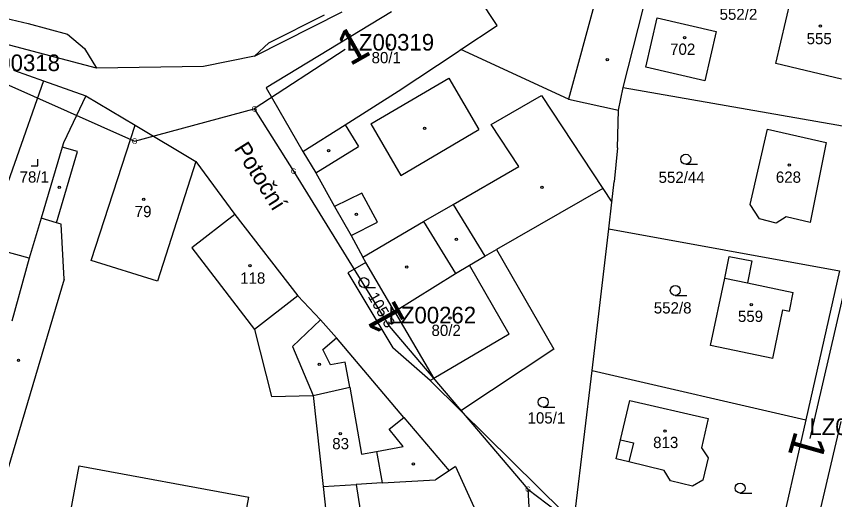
# Model space of a CAD drawing. Extents: x -738131 to -734179, y -1033447 to -1030078.
# Drawn here: x -735973.3 to -735849.9, y -1032032.1 to -1031959.2 of the extents above; entities that cross this region are included whole.
import ezdxf

# ---------------------------------------------------------------- set-up
doc = ezdxf.new("R2010")
doc.units = 0
for name, color, linetype in [('ftf_2010', 7, 'Continuous'), ('ftf_2050', 7, 'Continuous'), ('ftf_3010', 7, 'Continuous'), ('ftf_3010_ftf_3010_gtda_3015_gtda_3015_1', 7, 'Continuous'), ('ftf_3240', 7, 'Continuous'), ('ftf_nu', 7, 'Continuous'), ('Vrstva 1', 7, 'Continuous'), ('Vrstva 2', 7, 'Continuous'), ('Vrstva 3', 7, 'Continuous'), ('Vrstva 4', 7, 'Continuous'), ('Vrstva 5', 7, 'Continuous')]:
    doc.layers.add(name, color=color, linetype=linetype)

msp = doc.modelspace()

# ---------------------------------------------------------------- linework, layer by layer
at = {"layer": 'ftf_2010'}
for points in [[(-735923.72, -1031964.24), (-735937.43, -1031973.19)], [(-735853.59, -1032022.89), (-735843.74, -1031980.38)], [(-735896.17, -1032030.54), (-735890.35, -1032034.94), (-735881.54, -1032037.71)]]:
    msp.add_lwpolyline(points, dxfattribs=at)
at = {"layer": 'ftf_2050'}
for points in [[(-735980.93, -1031966.75), (-735955.51, -1031978.05), (-735937.43, -1031973.19), (-735931.52, -1031982.59), (-735917.1, -1032005.94)], [(-735917.1, -1032005.94), (-735896.17, -1032030.54)], [(-735896.17, -1032030.54), (-735893.12, -1032084.54)]]:
    msp.add_lwpolyline(points, dxfattribs=at)
at = {"layer": 'Vrstva 1'}
for points in [[(-735961.21, -1031967.08), (-736018.7, -1031951.81)], [(-735900.79, -1031960.62), (-735906.3, -1031952.23)], [(-735986.96, -1031956.67), (-735971.51, -1031960.34)], [(-735858.78, -1031966.37), (-735856.49, -1031956.68)], [(-735937.37, -1031965.26), (-735924.17, -1031958.55)], [(-735916.75, -1031958.57), (-735935.65, -1031970.03)], [(-735935.21, -1031963.22), (-735926.83, -1031959.03)], [(-735881.77, -1031969.95), (-735878.78, -1031958.13)], [(-735971.51, -1031960.34), (-735965.62, -1031961.95)], [(-735878.36, -1031966.91), (-735876.65, -1031959.47)], [(-735876.65, -1031959.47), (-735867.74, -1031961.53)], [(-735906.29, -1031964.27), (-735900.79, -1031960.62)], [(-735867.74, -1031961.53), (-735869.45, -1031968.95)], [(-735965.62, -1031961.95), (-735963.02, -1031964.11)], [(-735963.02, -1031964.11), (-735961.21, -1031967.08)], [(-735937.37, -1031965.26), (-735935.21, -1031963.22)], [(-735937.37, -1031965.26), (-735945.11, -1031966.83)], [(-735890.02, -1031971.71), (-735906.29, -1031964.27)], [(-735848.86, -1031968.72), (-735858.78, -1031966.37)], [(-735973.72, -1031967.37), (-735969.23, -1031968.95)], [(-735945.11, -1031966.83), (-735961.21, -1031967.08)], [(-735869.45, -1031968.95), (-735878.36, -1031966.91)], [(-735969.23, -1031968.95), (-735978.02, -1031993.89)], [(-735969.23, -1031968.95), (-735962.81, -1031971.21)], [(-735935.65, -1031970.03), (-735930.11, -1031979.64)], [(-735882.47, -1031973.38), (-735881.77, -1031969.95)], [(-735881.77, -1031969.95), (-735844.37, -1031976.51)], [(-735962.81, -1031971.21), (-735966.2, -1031978.32)], [(-735962.81, -1031971.21), (-735955.41, -1031975.66)], [(-735890.02, -1031971.71), (-735882.47, -1031973.38)], [(-735882.65, -1031979.08), (-735882.47, -1031973.38)], [(-735955.41, -1031975.66), (-735946.22, -1031981.15)], [(-735862.66, -1031987.59), (-735860.01, -1031976.28)], [(-735860.01, -1031976.28), (-735851.15, -1031978.27)], [(-735966.39, -1031978.96), (-735969.58, -1031989.67)], [(-735966.2, -1031978.32), (-735966.39, -1031978.96)], [(-735851.15, -1031978.27), (-735853.6, -1031990.31)], [(-735930.11, -1031979.64), (-735928.14, -1031982.86)], [(-735882.65, -1031979.08), (-735883.13, -1031984.22)], [(-735946.22, -1031981.15), (-735940.38, -1031989.1)], [(-735928.14, -1031982.86), (-735925.34, -1031987.91)], [(-735884.86, -1031985.2), (-735900.89, -1031994.4)], [(-735884.86, -1031985.2), (-735883.49, -1031987.28)], [(-735883.49, -1031987.28), (-735883.13, -1031984.22)], [(-735911.88, -1031990.2), (-735907.41, -1031987.6)], [(-735907.41, -1031987.6), (-735902.63, -1031995.4)], [(-735883.96, -1031991.27), (-735883.49, -1031987.28)], [(-735861.25, -1031989.8), (-735862.66, -1031987.59)], [(-735925.34, -1031987.91), (-735922.83, -1031992.3)], [(-735969.58, -1031989.67), (-735971.38, -1031995.71)], [(-735940.38, -1031989.1), (-735946.87, -1031994.13)], [(-735940.38, -1031989.1), (-735930.85, -1032001.38)], [(-735858.7, -1031990.42), (-735861.25, -1031989.8)], [(-735857.21, -1031989.47), (-735858.7, -1031990.42)], [(-735853.6, -1031990.31), (-735857.21, -1031989.47)], [(-735921.06, -1031995.58), (-735911.88, -1031990.2)], [(-735886.49, -1032012.63), (-735883.96, -1031991.27)], [(-735883.96, -1031991.27), (-735849.15, -1031997.63)], [(-735922.83, -1031992.3), (-735921.06, -1031995.58)], [(-735971.38, -1031995.71), (-735978.02, -1031993.89)], [(-735946.87, -1031994.13), (-735937.4, -1032006.46)], [(-735902.63, -1031995.4), (-735900.89, -1031994.4)], [(-735900.89, -1031994.4), (-735892.26, -1032009.45)], [(-735971.38, -1031995.71), (-735973.98, -1032005.19)], [(-735920.62, -1031996.34), (-735923.3, -1031997.93)], [(-735920.62, -1031996.34), (-735921.06, -1031995.58)], [(-735916.28, -1032003.73), (-735920.62, -1031996.34)], [(-735866.48, -1031998.72), (-735865.79, -1031995.43)], [(-735865.79, -1031995.43), (-735862.36, -1031996.13)], [(-735862.36, -1031996.13), (-735863.06, -1031999.44)], [(-735923.3, -1031997.93), (-735916.55, -1032009.23)], [(-735868.61, -1032008.87), (-735866.48, -1031998.72)], [(-735849.15, -1031997.63), (-735854.24, -1032020.1)], [(-735863.06, -1031999.44), (-735856.14, -1032000.89)], [(-735856.72, -1032003.69), (-735856.14, -1032000.89)], [(-735930.85, -1032001.38), (-735927.46, -1032005)], [(-735916.28, -1032003.73), (-735910.35, -1032013.83)], [(-735859.24, -1032010.84), (-735857.7, -1032003.48)], [(-735857.7, -1032003.48), (-735856.72, -1032003.69)], [(-735927.46, -1032005), (-735931.64, -1032009.01)], [(-735925.04, -1032007.7), (-735927.46, -1032005)], [(-735937.4, -1032006.46), (-735934.81, -1032016.56)], [(-735914.87, -1032019.71), (-735925.04, -1032007.7)], [(-735931.64, -1032009.01), (-735928.55, -1032016.39)], [(-735910.91, -1032014.16), (-735916.55, -1032009.23)], [(-735892.26, -1032009.45), (-735906.26, -1032018.74)], [(-735859.24, -1032010.84), (-735868.61, -1032008.87)], [(-735888.96, -1032033.55), (-735886.49, -1032012.63)], [(-735886.49, -1032012.63), (-735854.24, -1032020.1)], [(-735910.35, -1032013.83), (-735910.91, -1032014.16)], [(-735910.91, -1032014.16), (-735906.26, -1032018.74)], [(-735934.81, -1032016.56), (-735928.55, -1032016.39)], [(-735928.55, -1032016.39), (-735927.06, -1032030.11)], [(-735882.17, -1032023.1), (-735880.8, -1032017.15)], [(-735880.8, -1032017.15), (-735868.98, -1032019.87)], [(-735914.87, -1032019.71), (-735908.01, -1032027.75)], [(-735890.86, -1032033.93), (-735906.26, -1032018.74)], [(-735868.98, -1032019.87), (-735869.98, -1032024.28)], [(-735854.24, -1032020.1), (-735858.7, -1032039.76)], [(-735848.94, -1032020.31), (-735854.11, -1032042.18)], [(-735882.83, -1032025.98), (-735882.17, -1032023.1)], [(-735869.98, -1032024.28), (-735868.99, -1032025.83)], [(-735868.99, -1032025.83), (-735869.78, -1032029.16)], [(-735907.07, -1032027.13), (-735908.01, -1032027.75)], [(-735907.07, -1032027.13), (-735904.32, -1032033.19)], [(-735880.94, -1032026.43), (-735882.83, -1032025.98)], [(-735875.6, -1032027.72), (-735880.94, -1032026.43)], [(-735908.01, -1032027.75), (-735910.12, -1032029.14)], [(-735874.67, -1032029.29), (-735875.6, -1032027.72)], [(-735918.12, -1032029.6), (-735922.07, -1032029.83)], [(-735918.12, -1032029.6), (-735910.12, -1032029.14)], [(-735871.31, -1032030.08), (-735874.67, -1032029.29)], [(-735869.78, -1032029.16), (-735871.31, -1032030.08)], [(-735927.06, -1032030.11), (-735922.07, -1032029.83)], [(-735927.06, -1032030.11), (-735924.89, -1032050.16)], [(-735922.07, -1032029.83), (-735920.93, -1032036.93)]]:
    msp.add_lwpolyline(points, dxfattribs=at)
at = {"layer": 'Vrstva 3'}
for p, q in [((-735970.09, -1031981.78), (-735970.09, -1031980.78)), ((-735971.09, -1031981.78), (-735970.09, -1031981.78)), ((-735872.35, -1031981.54), (-735870.6, -1031981.54)), ((-735920.89, -1032000.14), (-735919.14, -1032000.14)), ((-735873.93, -1032001.32), (-735872.18, -1032001.32)), ((-735893.85, -1032018.17), (-735892.1, -1032018.17)), ((-735864.15, -1032031.12), (-735862.4, -1032031.12))]:
    msp.add_line(p, q, dxfattribs=at)
for centre in [(-735872.35, -1031980.79), (-735920.89, -1031999.39), (-735873.93, -1032000.57), (-735893.85, -1032017.42), (-735864.15, -1032030.37)]:
    msp.add_circle(centre, 0.75, dxfattribs=at)
at = {"layer": 'Vrstva 4'}
for points in [[(-735885.93, -1031956.55), (-735890.02, -1031971.71)], [(-735915.73, -1031970.51), (-735906.84, -1031964.63)], [(-735906.84, -1031964.63), (-735906.29, -1031964.27)], [(-735919.85, -1031975.47), (-735908.09, -1031968.57)], [(-735908.09, -1031968.57), (-735903.55, -1031976.32)], [(-735923.73, -1031975.59), (-735915.73, -1031970.51)], [(-735901.7, -1031975.55), (-735894.13, -1031971.16)], [(-735894.13, -1031971.16), (-735884.86, -1031985.2)], [(-735962.04, -1031996.06), (-735955.41, -1031975.66)], [(-735930.11, -1031979.64), (-735923.73, -1031975.59)], [(-735923.73, -1031975.59), (-735921.73, -1031978.85)], [(-735919.85, -1031975.47), (-735915.31, -1031983.22)], [(-735915.31, -1031983.22), (-735903.55, -1031976.32)], [(-735897.53, -1031981.87), (-735901.7, -1031975.55)], [(-735964.09, -1031979.63), (-735966.39, -1031978.96)], [(-735928.14, -1031982.86), (-735921.73, -1031978.85)], [(-735967.28, -1031990.37), (-735964.09, -1031979.63)], [(-735946.22, -1031981.15), (-735952.03, -1031999.15)], [(-735907.41, -1031987.6), (-735897.53, -1031981.87)], [(-735921.2, -1031985.89), (-735925.34, -1031987.91)], [(-735918.84, -1031990.27), (-735921.2, -1031985.89)], [(-735967.28, -1031990.37), (-735969.58, -1031989.67)], [(-735966.57, -1031990.58), (-735967.28, -1031990.37)], [(-735966.08, -1031998.87), (-735966.57, -1031990.58)], [(-735922.83, -1031992.3), (-735918.84, -1031990.27)], [(-735911.88, -1031990.2), (-735907.07, -1031998.04)], [(-735952.03, -1031999.15), (-735962.04, -1031996.06)], [(-735904.97, -1031996.74), (-735902.63, -1031995.4)], [(-735907.07, -1031998.04), (-735904.97, -1031996.74)], [(-735899, -1032007.14), (-735904.97, -1031996.74)], [(-735916.28, -1032003.73), (-735907.07, -1031998.04)], [(-735866.48, -1031998.72), (-735863.06, -1031999.44)], [(-735966.08, -1031998.87), (-735976.03, -1032032.11)], [(-735930.85, -1032001.38), (-735937.4, -1032006.46)], [(-735899, -1032007.14), (-735910.35, -1032013.83)], [(-735927.08, -1032009.46), (-735925.04, -1032007.7)], [(-735925.94, -1032011.78), (-735927.08, -1032009.46)], [(-735923.71, -1032011.39), (-735925.94, -1032011.78)], [(-735923.02, -1032015.18), (-735923.71, -1032011.39)], [(-735928.55, -1032016.39), (-735923.02, -1032015.18)], [(-735923.02, -1032015.18), (-735921.24, -1032025.25)], [(-735917.1, -1032021.5), (-735914.87, -1032019.71)], [(-735914.95, -1032024.11), (-735917.1, -1032021.5)], [(-735882.17, -1032023.1), (-735880.22, -1032023.54)], [(-735918.99, -1032024.85), (-735914.95, -1032024.11)], [(-735880.22, -1032023.54), (-735880.94, -1032026.43)], [(-735921.24, -1032025.25), (-735918.99, -1032024.85)], [(-735918.99, -1032024.85), (-735918.12, -1032029.6)], [(-735966.23, -1032040.01), (-735963.83, -1032027.01)], [(-735963.83, -1032027.01), (-735938.25, -1032031.74)], [(-735940.65, -1032044.74), (-735938.25, -1032031.74)]]:
    msp.add_lwpolyline(points, dxfattribs=at)
at = {"layer": 'Vrstva 5'}
for centre in [(-735852.04, -1031960.71), (-735872.53, -1031962.48), (-735917.17, -1031963.58), (-735884.2, -1031965.8), (-735911.74, -1031976.11), (-735926.22, -1031979.49), (-735856.74, -1031981.67), (-735966.85, -1031985.04), (-735894.05, -1031985.02), (-735954.09, -1031986.84), (-735922.02, -1031989.1), (-735906.94, -1031992.87), (-735938.09, -1031996.84), (-735914.44, -1031997.06), (-735862.46, -1032002.73), (-735907.92, -1032004.73), (-735972.99, -1032011.11), (-735927.63, -1032011.72), (-735924.46, -1032022.15), (-735875.46, -1032021.77), (-735913.43, -1032026.72)]:
    msp.add_circle(centre, 0.175, dxfattribs=at)

# ---------------------------------------------------------------- texts
at = {"layer": 'ftf_3010'}
for rotation, p in [(29.4452, (-735923.01, -1031966.82)), (119.0432, (-735914.51, -1032005.24)), (254.1269, (-735855.92, -1032021.56))]:
    msp.add_text('1', height=5.2, rotation=rotation, dxfattribs=at).set_placement(p)
at = {"layer": 'ftf_3010_ftf_3010_gtda_3015_gtda_3015_1'}
for s, p in [('LZ00319', (-735923.5, -1031964.41)), ('LZ00318', (-735979.93, -1031967.5)), ('LZ00262', (-735917.17, -1032005.54)), ('LZ00271', (-735853.7, -1032022.37))]:
    msp.add_text(s, height=2.5, dxfattribs=at).set_placement(p)
at = {"layer": 'ftf_3240'}
for p in [(-735937.83, -1031973.59), (-735955.91, -1031978.45), (-735931.92, -1031982.99), (-735896.57, -1032030.94)]:
    msp.add_text('G', height=0.8, dxfattribs=at).set_placement(p)
at = {"layer": 'ftf_nu'}
msp.add_text('Potoční', height=2.5, rotation=302.194, dxfattribs=at).set_placement((-735940.56, -1031979.19))
at = {"layer": 'Vrstva 2'}
for s, p in [('552/2', (-735867.25, -1031959.77)), ('555', (-735854.12, -1031963.45)), ('702', (-735874.71, -1031965.05)), ('80/1', (-735919.74, -1031966.32)), ('78/1', (-735972.82, -1031984.31)), ('552/44', (-735876.45, -1031984.36)), ('628', (-735858.76, -1031984.34)), ('79', (-735955.46, -1031989.52)), ('118', (-735939.56, -1031999.56)), ('552/8', (-735877.17, -1032004.05)), ('559', (-735864.48, -1032005.32)), ('80/2', (-735910.7, -1032007.44)), ('105/1', (-735896.21, -1032020.64)), ('83', (-735925.67, -1032024.52)), ('813', (-735877.27, -1032024.34))]:
    msp.add_text(s, height=1.7, dxfattribs=at).set_placement(p)
msp.add_text('105/3', height=1.7, rotation=299.5828, dxfattribs=at).set_placement((-735920.35, -1032001.46))

doc.saveas('drawing.dxf')
